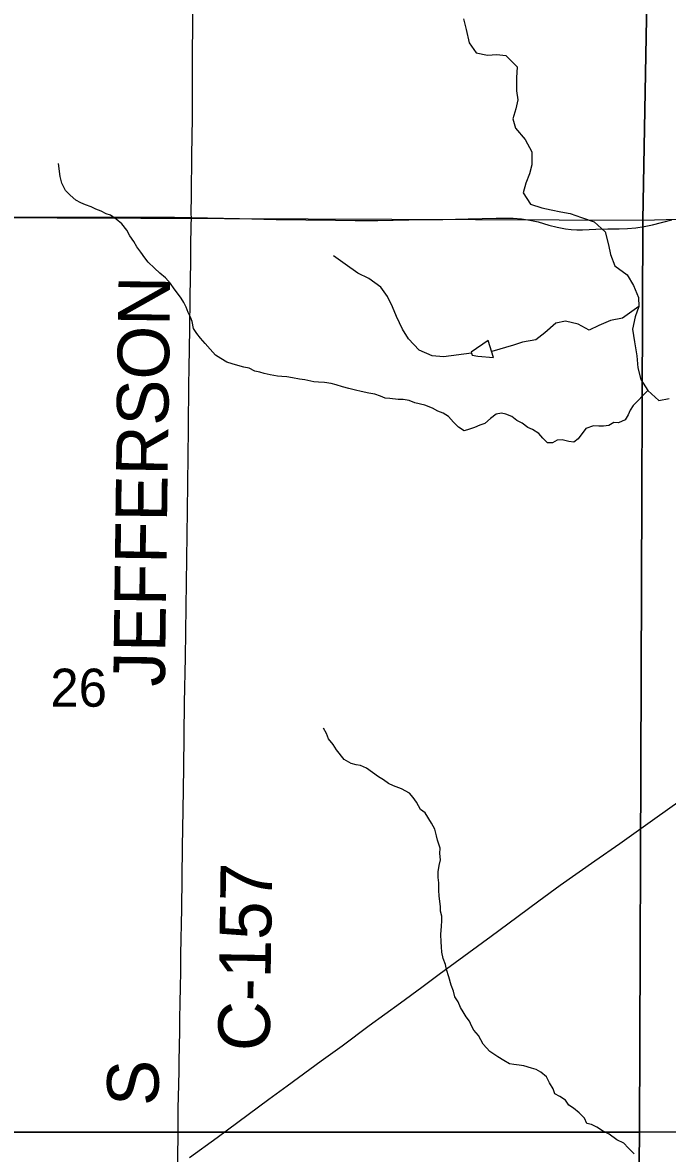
# Model space of a CAD drawing. Extents: x 0 to 34, y 0 to 22.
# Drawn here: x 3.95 to 4.659, y 16.861 to 18.105 of the extents above; entities that cross this region are included whole.
import ezdxf

# ---------------------------------------------------------------- set-up
doc = ezdxf.new("R2010")
doc.units = 0
for name, color, linetype in [('GM_X_County_Road', 7, 'Continuous'), ('GM_X_County_Road_Text', 7, 'Continuous'), ('GM_X_Minor_Lake', 7, 'Continuous'), ('GM_X_Minor_River', 7, 'Continuous'), ('GM_X_Section', 7, 'Continuous'), ('GM_X_Section_Text', 7, 'Continuous'), ('GM_X_State_Route', 7, 'Continuous'), ('GM_X_Township_Road', 7, 'Continuous')]:
    doc.layers.add(name, color=color, linetype=linetype)

msp = doc.modelspace()

# ---------------------------------------------------------------- linework, layer by layer
at = {"layer": 'GM_X_County_Road'}
for points in [[(4.1354, 17.891), (4.1352, 17.8945), (4.1354, 17.9162), (4.1358, 17.9597), (4.1364, 18.0001), (4.1364, 18.0187), (4.1366, 18.0684), (4.1368, 18.1057), (4.1371, 18.1523), (4.1375, 18.2238), (4.1376, 18.2455), (4.1378, 18.2735), (4.1381, 18.3045), (4.1385, 18.3542), (4.139, 18.3884), (4.139, 18.4101), (4.1404, 18.4971), (4.1405, 18.514)], [(4.1202, 16.8475), (4.1206, 16.8925), (4.1209, 16.9111), (4.1215, 16.9369), (4.1217, 16.9526), (4.122, 16.9657), (4.1223, 16.9765), (4.1223, 16.9836), (4.1224, 16.9916), (4.1224, 16.9997), (4.1226, 17.0117), (4.1229, 17.025), (4.1233, 17.0465), (4.1235, 17.059), (4.1238, 17.0807), (4.1246, 17.1304), (4.1256, 17.1987), (4.1261, 17.2391), (4.1268, 17.2857), (4.1278, 17.3571), (4.1287, 17.4068), (4.1296, 17.4627), (4.1301, 17.5156), (4.1309, 17.5684), (4.132, 17.6585), (4.1326, 17.7082), (4.1329, 17.7237), (4.1332, 17.7485), (4.1335, 17.7672), (4.1339, 17.8044), (4.1345, 17.8417), (4.1348, 17.8603), (4.1351, 17.882), (4.1354, 17.891)]]:
    msp.add_lwpolyline(points, dxfattribs=at)
at = {"layer": 'GM_X_Minor_Lake'}
for points in [[(4.4619, 17.7557), (4.4431, 17.7427), (4.4442, 17.7396), (4.4503, 17.7385), (4.4677, 17.7371)], [(4.4677, 17.7371), (4.4619, 17.7557)]]:
    msp.add_lwpolyline(points, dxfattribs=at)
at = {"layer": 'GM_X_Minor_River'}
for points in [[(4.4346, 18.1094), (4.4377, 18.0977), (4.4408, 18.0833), (4.4485, 18.0723), (4.461, 18.0697), (4.4712, 18.0702), (4.4814, 18.0691), (4.4936, 18.0566), (4.4929, 18.0445), (4.493, 18.0305), (4.4946, 18.0206), (4.4923, 18.0107), (4.489, 17.9997), (4.4917, 17.9891), (4.5024, 17.9767), (4.51, 17.9631), (4.5097, 17.949), (4.5071, 17.9391), (4.5034, 17.9289), (4.5004, 17.9182), (4.5085, 17.9058), (4.521, 17.9017), (4.5312, 17.8995), (4.5418, 17.8972), (4.5521, 17.8954), (4.5646, 17.8909), (4.5783, 17.8861), (4.5904, 17.8752), (4.5943, 17.8608), (4.5962, 17.8502), (4.6012, 17.838), (4.6146, 17.8279), (4.6218, 17.8162), (4.6272, 17.8029), (4.6276, 17.7931), (4.6235, 17.7817), (4.6206, 17.768), (4.6229, 17.7543), (4.6253, 17.7388), (4.6265, 17.7255), (4.6296, 17.7127), (4.6376, 17.7006), (4.6494, 17.6896), (4.6611, 17.692)], [(4.0643, 17.877), (4.0586, 17.8842), (4.0525, 17.8891), (4.0464, 17.8937), (4.0414, 17.8952), (4.0361, 17.8978), (4.03, 17.9), (4.0251, 17.9027), (4.0186, 17.9049), (4.0137, 17.9072), (4.008, 17.9102), (4.0019, 17.9155), (3.9969, 17.9208), (3.9927, 17.9288), (3.9908, 17.936), (3.9892, 17.9504)], [(4.6376, 17.7006), (4.6213, 17.6841), (4.6179, 17.6792), (4.6157, 17.6738), (4.6126, 17.6685), (4.6051, 17.665), (4.6001, 17.6654), (4.5945, 17.6623), (4.5888, 17.6616), (4.5835, 17.6615), (4.5778, 17.6619), (4.5691, 17.6588), (4.5608, 17.6474), (4.5559, 17.6439), (4.5505, 17.6446), (4.5433, 17.6465), (4.5376, 17.6461), (4.5327, 17.643), (4.527, 17.643), (4.5221, 17.6483), (4.5175, 17.6532), (4.5106, 17.6578), (4.5053, 17.66), (4.4992, 17.6646), (4.4935, 17.6676), (4.4878, 17.6721), (4.4813, 17.6747), (4.4764, 17.6759), (4.4707, 17.6747), (4.4643, 17.6697), (4.4582, 17.6644), (4.4525, 17.6624), (4.4469, 17.6598), (4.4412, 17.6582), (4.4355, 17.6563), (4.429, 17.6604), (4.4237, 17.6657), (4.4183, 17.6722), (4.4122, 17.6756), (4.4065, 17.6778), (4.4004, 17.6812), (4.3921, 17.6846), (4.3811, 17.6872), (4.375, 17.6895), (4.3681, 17.6906), (4.3628, 17.6909), (4.3537, 17.6917), (4.3484, 17.6924), (4.3434, 17.6943), (4.337, 17.6965), (4.3305, 17.6976), (4.3222, 17.6995), (4.3157, 17.701), (4.3085, 17.7028), (4.3016, 17.7047), (4.2944, 17.707), (4.2891, 17.7085), (4.2819, 17.7096), (4.2751, 17.7099), (4.2701, 17.7103), (4.2602, 17.7125), (4.2542, 17.7132), (4.2466, 17.7147), (4.2401, 17.7158), (4.2348, 17.7162), (4.2299, 17.7166), (4.2219, 17.718), (4.2154, 17.7195), (4.2105, 17.7207), (4.2052, 17.7221), (4.1987, 17.7252), (4.193, 17.7263), (4.1862, 17.7281), (4.1801, 17.73), (4.1744, 17.7319), (4.1675, 17.736), (4.1618, 17.7394), (4.1561, 17.7463), (4.1504, 17.7523), (4.1454, 17.7584), (4.1412, 17.7633), (4.1377, 17.769), (4.1362, 17.7766), (4.1343, 17.7815), (4.1316, 17.7864), (4.1296, 17.7925), (4.127, 17.7975), (4.1239, 17.8024), (4.1201, 17.8077), (4.1163, 17.8126), (4.1124, 17.8183), (4.1067, 17.8247), (4.1006, 17.8296), (4.0945, 17.8353), (4.0876, 17.8418), (4.0842, 17.8467), (4.0796, 17.8527), (4.0754, 17.8588), (4.072, 17.8645), (4.0674, 17.8709), (4.0643, 17.877)], [(4.4435, 17.7416), (4.4128, 17.7379), (4.4003, 17.739), (4.3859, 17.745), (4.3741, 17.7574), (4.3676, 17.768), (4.361, 17.782), (4.3564, 17.7926), (4.3511, 17.804), (4.3438, 17.8142), (4.3305, 17.8239), (4.3184, 17.8296), (4.3043, 17.8397), (4.2918, 17.8487)], [(4.6276, 17.7931), (4.6095, 17.7801), (4.5963, 17.7777), (4.5834, 17.7723), (4.5728, 17.767), (4.5607, 17.7737), (4.5467, 17.777), (4.5364, 17.7747), (4.524, 17.764), (4.5142, 17.7564), (4.4994, 17.754), (4.4896, 17.7505), (4.4657, 17.7436)], [(4.6224, 16.861), (4.6159, 16.8674), (4.6109, 16.8727), (4.6032, 16.8762), (4.5948, 16.8826), (4.5876, 16.8864), (4.5815, 16.8903), (4.5753, 16.8933), (4.5704, 16.8944), (4.5677, 16.9002), (4.562, 16.9062), (4.5558, 16.9112), (4.5505, 16.9146), (4.547, 16.9199), (4.5405, 16.9241), (4.5352, 16.9268), (4.5333, 16.9325), (4.5294, 16.939), (4.526, 16.9458), (4.5199, 16.9508), (4.5145, 16.9538), (4.5096, 16.9553), (4.5012, 16.9576), (4.4958, 16.9584), (4.4901, 16.9591), (4.4851, 16.9599), (4.479, 16.9637), (4.4725, 16.9675), (4.4637, 16.9736), (4.4564, 16.9816), (4.4511, 16.9911), (4.4461, 16.9968), (4.4434, 17.0018), (4.4411, 17.0067), (4.4377, 17.0116), (4.4342, 17.017), (4.4315, 17.0219), (4.4289, 17.028), (4.425, 17.0337), (4.4235, 17.0398), (4.4212, 17.0466), (4.4185, 17.0558), (4.4158, 17.0638), (4.415, 17.0691), (4.4123, 17.0759), (4.4108, 17.0828), (4.4104, 17.0888), (4.41, 17.0942), (4.4096, 17.1022), (4.4103, 17.1113), (4.4107, 17.1174), (4.4107, 17.1223), (4.4092, 17.128), (4.4092, 17.133), (4.408, 17.1444), (4.4076, 17.1508), (4.4076, 17.1592), (4.4068, 17.1649), (4.4068, 17.171), (4.4079, 17.1782), (4.4094, 17.1843), (4.4086, 17.1915), (4.409, 17.1972), (4.4059, 17.206), (4.4048, 17.2109), (4.4032, 17.2181), (4.3994, 17.2246), (4.3925, 17.236), (4.3875, 17.2398), (4.3829, 17.2478), (4.3791, 17.2528), (4.3753, 17.2577), (4.3665, 17.2623), (4.3577, 17.2657), (4.3523, 17.2684), (4.3466, 17.2722), (4.3413, 17.2756), (4.3344, 17.2805), (4.3279, 17.2851), (4.3214, 17.2882), (4.3164, 17.2889), (4.3111, 17.2904), (4.3034, 17.2946), (4.295, 17.3053), (4.2912, 17.3114), (4.2862, 17.3175), (4.2839, 17.3232), (4.2805, 17.3293)]]:
    msp.add_lwpolyline(points, dxfattribs=at)
at = {"layer": 'GM_X_Section'}
for points in [[(4.6433, 18.514), (4.6321, 17.8882), (5.6468, 17.9172), (5.6499, 18.8708), (5.6498, 18.8985), (4.6746, 18.9086), (4.6746, 18.514)], [(3.6261, 18.514), (3.6191, 17.892), (4.6321, 17.8882), (4.6433, 18.514)], [(5.6468, 17.9172), (5.6465, 17.841), (5.6459, 16.8927), (4.6282, 16.8848), (4.6321, 17.8882)], [(3.6191, 17.892), (4.6321, 17.8882), (4.6282, 16.8848), (3.6155, 16.8848)], [(3.6155, 16.8848), (4.6282, 16.8848), (4.6171, 15.8766), (3.6166, 15.8725), (3.6011, 15.8725)], [(5.6459, 16.8927), (5.644, 16.8278), (5.6379, 15.8781), (4.6171, 15.8766), (4.6282, 16.8848)]]:
    msp.add_lwpolyline(points, close=True, dxfattribs=at)
at = {"layer": 'GM_X_State_Route'}
msp.add_lwpolyline([(4.1333, 16.8569), (4.1635, 16.8788), (4.2205, 16.9209), (4.2405, 16.9359), (4.2779, 16.9633), (4.3012, 16.9798), (4.3307, 17.002), (4.3654, 17.0271), (4.3887, 17.0441), (4.408, 17.0585), (4.4253, 17.0713), (4.465, 17.1004), (4.4833, 17.1139), (4.5177, 17.1394), (4.541, 17.1563), (4.5792, 17.1833), (4.6065, 17.2025), (4.6451, 17.2297), (4.6732, 17.2495)], dxfattribs=at)
at = {"layer": 'GM_X_Township_Road'}
for points in [[(3.6233, 17.8916), (3.66, 17.8913), (3.7066, 17.891), (3.7439, 17.8911), (3.7843, 17.891), (3.8371, 17.891), (3.8713, 17.8912), (3.9179, 17.8913), (3.949, 17.8915), (3.9894, 17.8915), (4.0236, 17.8914), (4.0484, 17.8915), (4.0701, 17.8915), (4.0888, 17.8913), (4.1167, 17.8912), (4.1354, 17.891)], [(4.1354, 17.891), (4.1882, 17.8898), (4.2285, 17.8889), (4.2938, 17.8879), (4.3155, 17.8876), (4.3404, 17.8876), (4.3745, 17.8883), (4.4118, 17.8889), (4.4397, 17.8897), (4.4707, 17.8902), (4.4893, 17.8901), (4.4985, 17.8895), (4.5077, 17.8882), (4.5167, 17.8862), (4.5286, 17.8827), (4.5376, 17.8802), (4.5468, 17.8784), (4.553, 17.8777), (4.5593, 17.8773), (4.5655, 17.8774), (4.5801, 17.878), (4.5934, 17.8784), (4.6058, 17.8786), (4.6151, 17.879), (4.6243, 17.8798), (4.6336, 17.8811), (4.6427, 17.883), (4.6637, 17.8886)]]:
    msp.add_lwpolyline(points, dxfattribs=at)

# ---------------------------------------------------------------- texts
at = {"layer": 'GM_X_County_Road_Text'}
for s, height, rotation, p in [('JEFFERSON', 0.05682, 89.2508, (4.1061, 17.3747)), ('C-157', 0.05682, 89.1819, (4.2213, 16.9736)), ('S', 0.0568, 90, (4.0994, 16.9136))]:
    msp.add_text(s, height=height, rotation=rotation, dxfattribs=at).set_placement(p)
at = {"layer": 'GM_X_Section_Text'}
msp.add_text('26', height=0.04186, rotation=0, dxfattribs=at).set_placement((3.9801, 17.3528))

doc.saveas('drawing.dxf')
